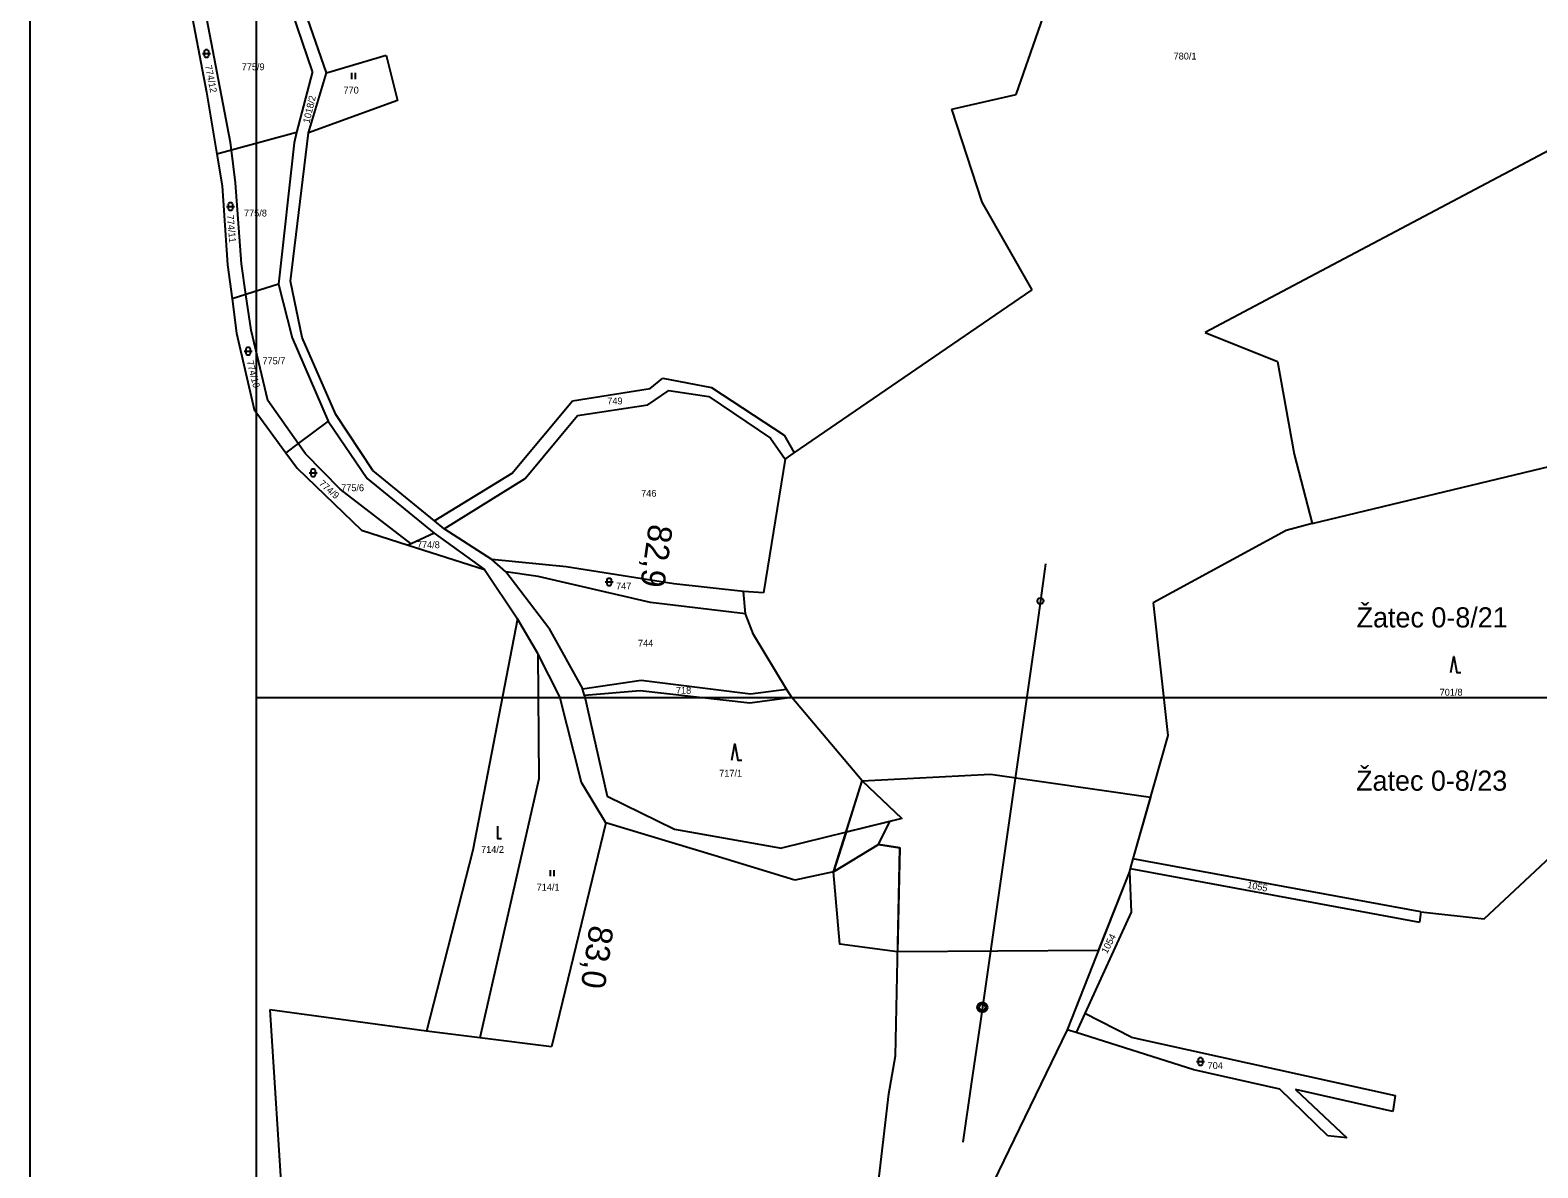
# Model space of a CAD drawing. Extents: x -801907 to -800293, y -1017000 to -1015684.
# Drawn here: x -801306.1 to -800931.6, y -1016616.9 to -1016334.3 of the extents above; entities that cross this region are included whole.
import ezdxf

# ---------------------------------------------------------------- set-up
doc = ezdxf.new("R2010")
doc.units = 0
for name, color, linetype in [('05a - kolej - svršek', 7, 'Continuous'), ('Default', 7, 'Continuous'), ('dočasné_zábory', 7, 'Continuous'), ('KLADY_ZMVM', 7, 'Continuous'), ('KN_HRANICE', 7, 'Continuous'), ('KN_KULTURY', 7, 'Continuous'), ('KN_PARCELY', 7, 'Continuous'), ('LEGENDA', 7, 'Continuous'), ('obvod_stavby', 7, 'Continuous'), ('Vrstva 7', 7, 'Continuous'), ('Železniční svršek', 7, 'Continuous')]:
    doc.layers.add(name, color=color, linetype=linetype)

# ---------------------------------------------------------------- blocks, each defined once
blk = doc.blocks.new('302')
at = {"layer": 'Default'}
blk.add_lwpolyline([(0, 3), (0, 0), (1, 0)], dxfattribs=at)
blk = doc.blocks.new('306')
at = {"layer": 'Default'}
for p, q in [((-0.5, 1.5), (-0.5, 0)), ((0.5, 0), (0.5, 1.5))]:
    blk.add_line(p, q, dxfattribs=at)
blk = doc.blocks.new('308')
at = {"layer": 'Default'}
blk.add_lwpolyline([(-0.75, 0), (0, 4), (0.75, 0), (1.75, 0)], dxfattribs=at)
blk = doc.blocks.new('316')
at = {"layer": 'Default'}
for points in [[(-1, 1), (0.27, 1), (1, 1)], [(-0.5, 1.5), (-0.4, 1.79), (-0.15, 1.97), (0.16, 1.97), (0.41, 1.79), (0.51, 1.5), (0.51, 0.5), (0.41, 0.21), (0.16, 0.03), (-0.15, 0.03), (-0.4, 0.21), (-0.5, 0.5), (-0.5, 1.5)]]:
    blk.add_lwpolyline(points, dxfattribs=at)
blk = doc.blocks.new('C512')
at = {"layer": 'Default'}
for radius in [1.25, 0.752]:
    blk.add_circle((0, 0), radius, dxfattribs=at)
blk = doc.blocks.new('C513_1')
at = {"layer": 'Default'}
blk.add_circle((0, 0), 0.75, dxfattribs=at)

msp = doc.modelspace()

# ---------------------------------------------------------------- linework, layer by layer
at = {"layer": 'dočasné_zábory'}
for points in [[(-801103.44, -1016533.5), (-801099.39, -1016520.76), (-801089.6, -1016530.05), (-801103.44, -1016533.5)], [(-801103.44, -1016533.5), (-801106.57, -1016543.36), (-801095.34, -1016536.52), (-801092.56, -1016530.79), (-801103.44, -1016533.5), (-801106.57, -1016543.36)], [(-801106.57, -1016543.36), (-801095.34, -1016536.52), (-801090.08, -1016537.39), (-801090.62, -1016563.22), (-801105.01, -1016561.32), (-801106.57, -1016543.36)]]:
    msp.add_lwpolyline(points, dxfattribs=at)
at = {"layer": 'KLADY_ZMVM'}
msp.add_line((-801250, -1016500), (-800625, -1016500), dxfattribs=at)
msp.add_lwpolyline([(-801250, -1016000), (-801250, -1016500), (-801250, -1017000)], dxfattribs=at)
at = {"layer": 'KN_HRANICE'}
for p, q in [((-801061.14, -1016350.27), (-801047.99, -1016312.24)), ((-801235.95, -1016344.57), (-801243.11, -1016323.66)), ((-801232.53, -1016344.87), (-801240.17, -1016322.77)), ((-801266.91, -1016325.63), (-801262.33, -1016349.67)), ((-801256.32, -1016362.14), (-801263.32, -1016325.64)), ((-801232.53, -1016344.87), (-801217.71, -1016340.48)), ((-801217.71, -1016340.48), (-801214.86, -1016351.72)), ((-800888.88, -1016342.96), (-800989.55, -1016396.29)), ((-801235.95, -1016344.57), (-801239.91, -1016359.71)), ((-801237.01, -1016359.78), (-801232.53, -1016344.87)), ((-801262.33, -1016349.67), (-801259.75, -1016365.1)), ((-801077.17, -1016353.9), (-801061.14, -1016350.27)), ((-801214.86, -1016351.72), (-801237.01, -1016359.78)), ((-801069.63, -1016376.99), (-801077.17, -1016353.9)), ((-801256.08, -1016364.1), (-801256.32, -1016362.14)), ((-801239.91, -1016359.71), (-801256.08, -1016364.1)), ((-801241.46, -1016396.62), (-801237.01, -1016359.78)), ((-801239.91, -1016359.71), (-801240.57, -1016362.23)), ((-801256.08, -1016364.1), (-801259.75, -1016365.1)), ((-801259.75, -1016365.1), (-801258.44, -1016372.97)), ((-801255.07, -1016372.22), (-801256.08, -1016364.1)), ((-801240.57, -1016362.23), (-801244.39, -1016397.38)), ((-801258.44, -1016372.97), (-801257.05, -1016392.52)), ((-801253.58, -1016392.3), (-801255.07, -1016372.22)), ((-801057.23, -1016398.8), (-801069.63, -1016376.99)), ((-801257.05, -1016392.52), (-801255.96, -1016400.96)), ((-801252.5, -1016399.89), (-801253.58, -1016392.3)), ((-801244.39, -1016397.38), (-801252.5, -1016399.89)), ((-801244.39, -1016397.38), (-801241.06, -1016410.72)), ((-801238.53, -1016410.63), (-801241.46, -1016396.62)), ((-801116.28, -1016439.27), (-801057.23, -1016398.8)), ((-800989.55, -1016396.29), (-801014.25, -1016409.38)), ((-801252.5, -1016399.89), (-801255.96, -1016400.96)), ((-801255.96, -1016400.96), (-801254.86, -1016409.5)), ((-801251.24, -1016408.75), (-801252.5, -1016399.89)), ((-801254.86, -1016409.5), (-801250.45, -1016428.49)), ((-801247.06, -1016426.26), (-801251.24, -1016408.75)), ((-801241.06, -1016410.72), (-801232.1, -1016431.41)), ((-801230.15, -1016429.74), (-801238.53, -1016410.63)), ((-801014.25, -1016409.38), (-800996.24, -1016416.56)), ((-800996.24, -1016416.56), (-800992.09, -1016439.62)), ((-801152.11, -1016423.31), (-801148.96, -1016420.73)), ((-801148.96, -1016420.73), (-801136.85, -1016423.02)), ((-801171.38, -1016426.36), (-801152.11, -1016423.31)), ((-801152.7, -1016427.3), (-801147.48, -1016423.8)), ((-801147.48, -1016423.8), (-801137.53, -1016425.26)), ((-801137.53, -1016425.26), (-801122.21, -1016435.63)), ((-801136.85, -1016423.02), (-801118.82, -1016434.86)), ((-801250.45, -1016428.49), (-801242.64, -1016439.22)), ((-801239.53, -1016436.92), (-801247.06, -1016426.26)), ((-801186.46, -1016444.4), (-801171.38, -1016426.36)), ((-801170.12, -1016429.97), (-801152.7, -1016427.3)), ((-801232.1, -1016431.41), (-801239.53, -1016436.92)), ((-801232.1, -1016431.41), (-801222.43, -1016445.62)), ((-801221.02, -1016443.67), (-801230.15, -1016429.74)), ((-801183.14, -1016445.59), (-801170.12, -1016429.97)), ((-801239.53, -1016436.92), (-801242.64, -1016439.22)), ((-801237.71, -1016439.5), (-801239.53, -1016436.92)), ((-801122.21, -1016435.63), (-801118.58, -1016440.85)), ((-801118.82, -1016434.86), (-801116.28, -1016439.27)), ((-801242.64, -1016439.22), (-801239.82, -1016443.1)), ((-801229.11, -1016448.31), (-801237.71, -1016439.5)), ((-801118.58, -1016440.85), (-801123.97, -1016474)), ((-801118.58, -1016440.85), (-801116.28, -1016439.27)), ((-800992.09, -1016439.62), (-800987.67, -1016456.78)), ((-801239.82, -1016443.1), (-801223.83, -1016458.49)), ((-801205.69, -1016456.16), (-801221.02, -1016443.67)), ((-801186.46, -1016444.4), (-801205.69, -1016456.16)), ((-800987.67, -1016456.78), (-800928.47, -1016442.57)), ((-801211.44, -1016461.84), (-801229.11, -1016448.31)), ((-801222.43, -1016445.62), (-801205.74, -1016459.23)), ((-801203.29, -1016458.12), (-801183.14, -1016445.59)), ((-801223.83, -1016458.49), (-801212.17, -1016462.19)), ((-801205.74, -1016459.23), (-801211.44, -1016461.84)), ((-801205.74, -1016459.23), (-801193.22, -1016468.21)), ((-801203.29, -1016458.12), (-801205.69, -1016456.16)), ((-801191.45, -1016465.73), (-801203.29, -1016458.12)), ((-800994.11, -1016458.53), (-801027.13, -1016476.53)), ((-800987.67, -1016456.78), (-800994.11, -1016458.53)), ((-801211.44, -1016461.84), (-801212.17, -1016462.19)), ((-801212.17, -1016462.19), (-801193.22, -1016468.21)), ((-801172.97, -1016467.58), (-801191.45, -1016465.73)), ((-801187.97, -1016468.83), (-801191.45, -1016465.73)), ((-801193.22, -1016468.21), (-801185.05, -1016480.49)), ((-801179.9, -1016469.93), (-801187.97, -1016468.83)), ((-801177.23, -1016482.84), (-801187.97, -1016468.83)), ((-801151.99, -1016476.42), (-801179.9, -1016469.93)), ((-801146.21, -1016471.77), (-801172.97, -1016467.58)), ((-801128.93, -1016473.72), (-801146.21, -1016471.77)), ((-801128.43, -1016479.26), (-801128.93, -1016473.72)), ((-801123.97, -1016474), (-801128.93, -1016473.72)), ((-801128.43, -1016479.26), (-801151.99, -1016476.42)), ((-801027.13, -1016476.53), (-801023.48, -1016509.45)), ((-801185.05, -1016480.49), (-801196.12, -1016537.94)), ((-801179.97, -1016489.06), (-801185.05, -1016480.49)), ((-801126.4, -1016484.41), (-801128.43, -1016479.26)), ((-801177.23, -1016482.84), (-801168.91, -1016497.9)), ((-801118.21, -1016497.93), (-801126.4, -1016484.41)), ((-801174.55, -1016499.85), (-801179.97, -1016489.06)), ((-801179.97, -1016489.06), (-801179.72, -1016520.25)), ((-801168.91, -1016497.9), (-801154.35, -1016495.73)), ((-801154.35, -1016495.73), (-801127.14, -1016499.11)), ((-801169.16, -1016521.13), (-801174.55, -1016499.85)), ((-801168.4, -1016499.55), (-801168.91, -1016497.9)), ((-801154.54, -1016498.41), (-801168.4, -1016499.55)), ((-801168.4, -1016499.55), (-801162.75, -1016524.53)), ((-801127.33, -1016501.46), (-801154.54, -1016498.41)), ((-801116.94, -1016500.02), (-801127.33, -1016501.46)), ((-801127.14, -1016499.11), (-801118.21, -1016497.93)), ((-801116.94, -1016500.02), (-801118.21, -1016497.93)), ((-801099.39, -1016520.76), (-801116.94, -1016500.02)), ((-801023.48, -1016509.45), (-801032.15, -1016540.1)), ((-801179.72, -1016520.25), (-801194.41, -1016584.56)), ((-801163.14, -1016531.12), (-801169.16, -1016521.13)), ((-801089.6, -1016530.05), (-801099.39, -1016520.76)), ((-801162.75, -1016524.53), (-801146.04, -1016532.72)), ((-801089.6, -1016530.05), (-801092.56, -1016530.79)), ((-801163.14, -1016531.12), (-801176.64, -1016586.76)), ((-801136.16, -1016539.31), (-801163.14, -1016531.12)), ((-801146.04, -1016532.72), (-801119.48, -1016537.49)), ((-801092.56, -1016530.79), (-801119.48, -1016537.49)), ((-801095.34, -1016536.52), (-801092.56, -1016530.79)), ((-801196.12, -1016537.94), (-801207.69, -1016582.91)), ((-801095.34, -1016536.52), (-801106.57, -1016543.36)), ((-801090.08, -1016537.39), (-801095.34, -1016536.52)), ((-801091.16, -1016589.05), (-801090.08, -1016537.39)), ((-801116.15, -1016545.38), (-801136.16, -1016539.31)), ((-801032.15, -1016540.1), (-801032.82, -1016542.48)), ((-800960.64, -1016553.29), (-801032.15, -1016540.1)), ((-800944.95, -1016554.98), (-800927.12, -1016538.33)), ((-801106.57, -1016543.36), (-801116.15, -1016545.38)), ((-801033.04, -1016543.25), (-801048.49, -1016582.57)), ((-801032.82, -1016542.48), (-801033.04, -1016543.25)), ((-801033.04, -1016543.25), (-801032.63, -1016553.37)), ((-801032.82, -1016542.48), (-800961, -1016555.83)), ((-801032.63, -1016553.37), (-801044.11, -1016578.55)), ((-800960.64, -1016553.29), (-800961, -1016555.83)), ((-800960.64, -1016553.29), (-800944.95, -1016554.98)), ((-801246.59, -1016577.62), (-801245.16, -1016599.53)), ((-801207.69, -1016582.91), (-801246.59, -1016577.62)), ((-801044.11, -1016578.55), (-801046.26, -1016583.28)), ((-801032.64, -1016584.41), (-801044.11, -1016578.55)), ((-801194.41, -1016584.56), (-801207.69, -1016582.91)), ((-801048.49, -1016582.57), (-801068.25, -1016623.2)), ((-801046.26, -1016583.28), (-801048.49, -1016582.57)), ((-801176.64, -1016586.76), (-801194.41, -1016584.56)), ((-801017.05, -1016592.55), (-801046.26, -1016583.28)), ((-801032.64, -1016584.41), (-800967.03, -1016598.88)), ((-801092.82, -1016598.49), (-801091.16, -1016589.05)), ((-800995.66, -1016597.3), (-801017.05, -1016592.55)), ((-800983.76, -1016608.9), (-800995.66, -1016597.3)), ((-800967.59, -1016602.85), (-800991.79, -1016597.39)), ((-800991.79, -1016597.39), (-800979, -1016609.4)), ((-801245.16, -1016599.53), (-801243.27, -1016628.57)), ((-801096.7, -1016632.06), (-801092.82, -1016598.49)), ((-800967.03, -1016598.88), (-800967.59, -1016602.85)), ((-800979, -1016609.4), (-800983.76, -1016608.9))]:
    msp.add_line(p, q, dxfattribs=at)
at = {"layer": 'LEGENDA'}
msp.add_lwpolyline([(-801306.12, -1016323.56), (-800712.12, -1016323.56), (-800712.12, -1016743.56), (-801306.12, -1016743.56)], close=True, dxfattribs=at)
at = {"layer": 'obvod_stavby'}
msp.add_lwpolyline([(-801099.39, -1016520.76), (-801067.53, -1016519.1), (-801027.82, -1016524.78), (-801032.15, -1016540.1), (-801032.82, -1016542.48), (-801033.04, -1016543.25), (-801040.77, -1016562.91), (-801090.62, -1016563.22), (-801105.01, -1016561.32), (-801106.57, -1016543.36), (-801099.39, -1016520.76)], dxfattribs=at)
at = {"layer": 'Železniční svršek'}
msp.add_lwpolyline([(-801053.85, -1016466.85), (-801055.91, -1016481.4), (-801057.88, -1016495.24), (-801059.95, -1016509.7), (-801062.03, -1016524.24), (-801064.02, -1016538.14), (-801066, -1016552.04), (-801068.07, -1016566.48), (-801070.07, -1016580.45), (-801072.31, -1016596.09), (-801074.39, -1016610.52)], dxfattribs=at)

# ---------------------------------------------------------------- block references
at = {"layer": '05a - kolej - svršek'}
for name, p, rotation in [('C513_1', (-801055.15, -1016476.05), -98.06617219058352), ('C512', (-801069.57, -1016576.99), -98.19442411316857)]:
    msp.add_blockref(name, p, dxfattribs=dict(at, rotation=rotation))
at = {"layer": 'KN_KULTURY'}
for name, p in [('316', (-801262.33, -1016341.07)), ('306', (-801225.78, -1016346.4)), ('316', (-801256.37, -1016379.06)), ('316', (-801251.96, -1016415)), ('316', (-801235.81, -1016445.22)), ('316', (-801162.28, -1016472.33)), ('308', (-800952.48, -1016493.82)), ('308', (-801131.06, -1016515.56)), ('302', (-801190.03, -1016535.01)), ('306', (-801176.4, -1016544.38)), ('316', (-801015.36, -1016591.46))]:
    msp.add_blockref(name, p, dxfattribs=at)

# ---------------------------------------------------------------- texts
at = {"layer": 'KLADY_ZMVM'}
for s, p in [('Žatec 0-8/21', (-800976.6, -1016482.62)), ('Žatec 0-8/23', (-800976.72, -1016523.18))]:
    msp.add_text(s, height=5, dxfattribs=at).set_placement(p)
at = {"layer": 'KN_PARCELY'}
for s, rotation, p in [('774/12', 281.208, (-801262.69, -1016343.11)), ('1018/2', 76.604, (-801236.73, -1016357.51)), ('774/11', 275.421, (-801257.28, -1016380.18)), ('774/10', 284.187, (-801252.34, -1016416.53)), ('774/9', 318.565, (-801234.53, -1016447.1)), ('1055', 348.817, (-801003.87, -1016547.3)), ('1054', 62.624, (-801038.61, -1016563.8))]:
    msp.add_text(s, height=1.7, rotation=rotation, dxfattribs=at).set_placement(p)
for s, p in [('775/9', (-801253.56, -1016344.21)), ('780/1', (-801022.06, -1016341.55)), ('770', (-801228.28, -1016350.01)), ('775/8', (-801252.99, -1016380.54)), ('775/7', (-801248.41, -1016417.25)), ('749', (-801162.75, -1016427.21)), ('775/6', (-801228.86, -1016448.78)), ('746', (-801154.33, -1016450.16)), ('774/8', (-801210.04, -1016462.93)), ('747', (-801160.56, -1016473.18)), ('744', (-801155.13, -1016487.4)), ('718', (-801145.69, -1016499.1)), ('701/8', (-800955.97, -1016499.57)), ('717/1', (-801134.95, -1016519.69)), ('714/2', (-801194.09, -1016538.62)), ('714/1', (-801180.29, -1016547.99)), ('704', (-801013.62, -1016592.31))]:
    msp.add_text(s, height=1.7, dxfattribs=at).set_placement(p)
at = {"layer": 'Vrstva 7'}
for s, rotation, p in [('82,9', 261.9338, (-801152.38, -1016456.75)), ('83,0', 261.8056, (-801167.1, -1016556.4))]:
    msp.add_text(s, height=6, rotation=rotation, dxfattribs=at).set_placement(p)

doc.saveas('drawing.dxf')
